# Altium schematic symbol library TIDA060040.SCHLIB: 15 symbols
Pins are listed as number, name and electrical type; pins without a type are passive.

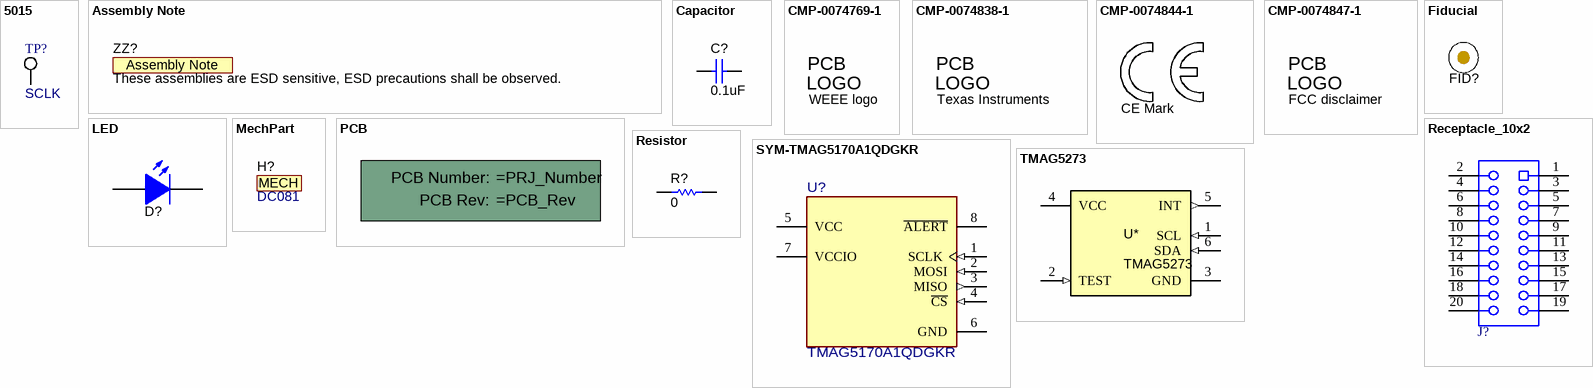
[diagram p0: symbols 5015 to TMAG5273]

## 5015
designator TP?, comment SCLK
Test Point, Miniature, SMT; Manufacturer: Keystone; PartNumber: 5015; CNHeader: FALSE; Green_Lifecycle: Active; Green_REACh: Passed; CT: TRUE
footprint Testpoint_Keystone_Miniature (Miniature SMT test point)
pins: 1

## Assembly Note
designator ZZ?, comment These assemblies are ESD sensitive, ESD precautions shall be observed.  (no BOM)
CompType: AssemblyNote
footprint AssemblyNote (Assembly Note)

## Capacitor
designator C?, comment ValueDisplayed: 0.1uF  (hidden comment: GRM155R71H104ME14D)
CAP, CERM, 0.1 uF, 50 V, +/- 20%, X7R, 0402; Manufacturer: MuRata; Polarized: N; CompType: Capacitor; Value: 0.1uF; U/M: EA; Cap_F: 100nF; Value1: Unknown; VDC_V: 50V; TaMin_C: -55°C; TaMax_C: 125°C; Cap_Case: 0402; SizeArea_mm2: 0.5; SizeAreaWB_mm2: 3; SizeX_mm: 1; SizeZ_mm: 0.6; AEC Category: Q200
footprint 0402 (0402 from SM-752 data)
footprint 0402S (Based on C0402S footprint from PADS legacy)
footprint 0402L (0402 from SM-752 data)
footprint 0402M (0402 from SM-752 data)
pins: 1, 2

## CMP-0074769-1
designator Logo?, comment WEEE logo  (no BOM)
footprint WEEE_Minimum (WEEElie bin)

## CMP-0074838-1
designator Logo?, comment Texas Instruments  (no BOM)
Texas Instrument Corporate Signature; SymbolCreator: a0412235; Lib Reference: TI_Logo; Library Reference: Logo
footprint TI_Horizontal_Overlay_Medium
footprint TI_Horizontal_Overlay_Small
footprint TI_Stacked_SolderMask_Small
footprint TI_Stacked_SolderMask_Small_Vertical
footprint TI_Symbol_Overlay_Medium
footprint TI_Symbol_Overlay_Small
footprint TI_Symbol_SolderMask_Medium
footprint TI_Symbol_SolderMask_Small
footprint TI_Horizontal_SolderMask_Medium
footprint TI_Horizontal_SolderMask_Small
footprint TI_Stacked_Overlay_Medium
footprint TI_Stacked_Overlay_Medium_Vertical
footprint TI_Stacked_Overlay_Small
footprint TI_Stacked_Overlay_Small_Vertical
footprint TI_Stacked_SolderMask_Medium
footprint TI_Stacked_SolderMask_Medium_Vertical

## CMP-0074844-1
designator Logo?, comment CE Mark  (no BOM)
SymbolCreator: a0412235
footprint CE_Mark_5mm (Minimum text height for CE Mark)
footprint CE_Mark_10mm (Double the minimum text height for CE Mark)

## CMP-0074847-1
designator Logo?, comment FCC disclaimer  (no BOM)
FCC_disclaimer; Library Reference: Logo
footprint FCC_disclaimer
footprint FCC_disclaimer_stacked

## Fiducial
designator FID?  (value not drawn)
Fiducial mark.  There is nothing to buy or mount.
footprint Fiducial10-30
footprint Fiducial15-30
footprint Fiducial10-20
footprint Fiducial20-40
footprint Fiducial6.4-20

## LED
designator D?, comment POWER ON  (value not drawn)
LED, White, SMD; PartNumber: VAOL-S8WR4; Manufacturer: Visual Communications Company, LLC; Type: InGaN; Value1: W; Io_A: 5mA; Vf_V: 2.925V
footprint VAOL-0805_White (Visual Communications)
pins: 1 A, 2 K

## MechPart
designator H?, comment DC081  (mechanical)
Kitting Item: PAMB Controller; Manufacturer: Texas Instruments; CompType: Mechanical

## PCB
designator !PCB?, comment Printed Circuit Board  (value not drawn)  (mechanical)
Manufacturer: Any; CompType: PCB
1 alternate drawing of the same symbol

## Receptacle_10x2
designator J?, comment SSQ-110-03-G-D  (value not drawn)
Receptacle, 2.54mm, 10x2, Gold, TH; Manufacturer: Samtec; Pitch_mm: 2.54; Cert_VDE: N; Gender: Female; Cert_CSA: Y; Current_A: 6.3A; Voltage_V: 550V; CT: True; Row_Count: 2; CompType: Socket Strip; CNHeader: False
footprint Samtec_SSQ-110-03-x-D (Receptacle, 2.54mm, 10x2, TH)
pins: 1, 2, 3, 4, 5, 6, 7, 8, 9, 10, 11, 12, 13, 14, 15, 16, 17, 18, 19, 20

## Resistor
designator R?, comment ValueDisplayed: 0  (hidden comment: MCT06030Z0000ZP500)
RES, 0, 5%, 0.125 W, 0603; Manufacturer: Vishay/Beyschlag; Power_W: 125mW; TempCo: ppm/C; Value_Code: 0000; U/M: EA; Value: 0; EIA_Code: E24; SizeX_mm: 1.6; SizeY_mm: 0.8; SizeZ_mm: 1; Value2: 0.125W; SizeArea_mm2: 1.28; CompType: Resistor; AEC Qualified: N; AEC Category: Q200
footprint 0603 (0603 from SM-752 data)
footprint 0603_HV (Ernesto recommended land pattern.  26 mil between pads.)
footprint 0603L (0603 from SM-752 data)
footprint 0603S
footprint 0603M (0603 from SM-752 data)
pins: 1, 2

## SYM-TMAG5170A1QDGKR
designator U?, comment TMAG5170A1QDGKR
3-Axis Linear Hall Effect Sensor With SPI Interface; Manufacturer: Texas Instruments; TJmax_C: +170°C; SizeZ_mm: 1.1mm; Operating Supply Current: 0.000005-4mA; Standoff Height: 0.05mm; Min Supply Voltage: 1.65V; Max Supply Voltage: 5.5V; AEC Grade: Grade 0; AEC Qualified: Yes
footprint DGK0008A-MFG
footprint DGK0008A-IPC_C
footprint DGK0008A-IPC_B
footprint DGK0008A-IPC_A
pins: 1 SCLK (in), 2 MOSI (in), 3 MISO (out), 4 ~{CS} (in), 5 VCC (power), 6 GND (power), 7 VCCIO (power), 8 ~{ALERT} (oc)

## TMAG5273
designator U*
3-Axis Linear Hall Effect Sensor With I2C Interface
footprint SOP6
pins: 1 SCL (in), 2 TEST (in), 3 GND (power), 4 VCC (power), 5 INT (out), 6 SDA (in)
